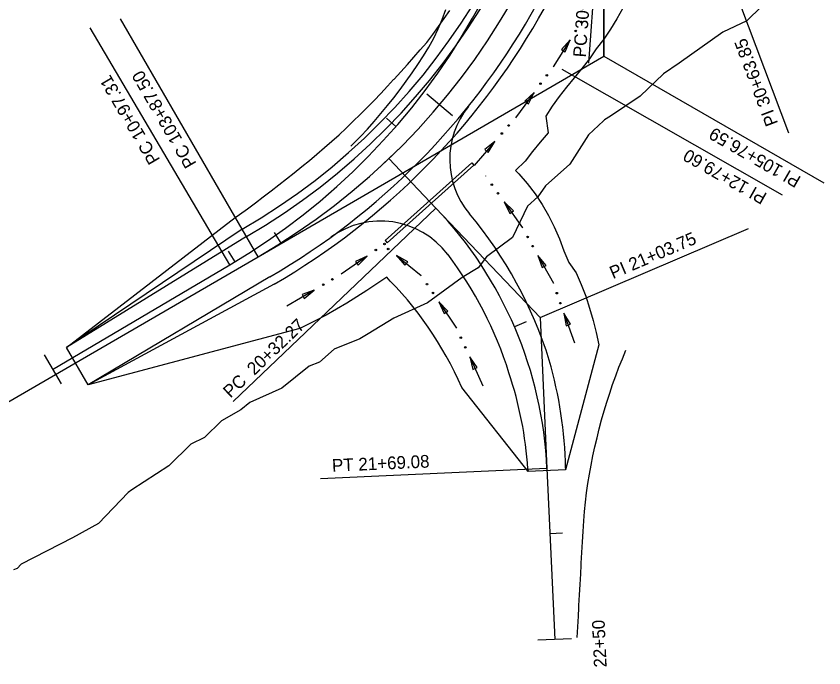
# Model space of a CAD drawing. Extents: x 1395202 to 1465904, y 1787951 to 1846942.
# Drawn here: x 1405502.4 to 1405884.5, y 1842049.9 to 1842358 of the extents above; entities that cross this region are included whole.
import ezdxf

# ---------------------------------------------------------------- set-up
doc = ezdxf.new("R2010")
doc.units = 0
for name, color, linetype in [('R_Drainage', 7, 'Continuous'), ('R_Horiz Alg Tangents', 7, 'Continuous'), ('R_Horz Alg', 7, 'Continuous'), ('R_Horz Alg Annot', 7, 'Continuous'), ('R_Horz Alg Stationing', 7, 'Continuous'), ('R_Perimeter', 7, 'Continuous'), ('R_Proposed Lane', 7, 'Continuous'), ('R_Proposed Shoulder', 7, 'Continuous'), ('R_SFHA', 7, 'Continuous'), ('R_Special Ditch', 7, 'Continuous'), ('R_Temp Perimeter', 7, 'Continuous'), ('R_Temp_Horz Alg', 7, 'Continuous'), ('R_Temp_Horz Alg Annot', 7, 'Continuous'), ('R_Temp_Horz Alg Stationing', 7, 'Continuous')]:
    doc.layers.add(name, color=color, linetype=linetype)

msp = doc.modelspace()

# ---------------------------------------------------------------- linework, layer by layer
at = {"layer": 'R_Drainage'}
for p, q in [((1405717.91, 1842288.66), (1405676.92, 1842251.99)), ((1405677.92, 1842250.87), (1405718.91, 1842287.54)), ((1405717.91, 1842288.66), (1405718.91, 1842287.54)), ((1405676.92, 1842251.99), (1405677.92, 1842250.87))]:
    msp.add_line(p, q, dxfattribs=at)
at = {"layer": 'R_Horiz Alg Tangents'}
for p, q in [((1405780.46, 1842339.07), (1405780.08, 1842528.16)), ((1405616.87, 1842244.24), (1405780.46, 1842339.07)), ((1405700.98, 1842267.28), (1405750.29, 1842215.53)), ((1405750.29, 1842215.53), (1405753.51, 1842144.12))]:
    msp.add_line(p, q, dxfattribs=at)
at = {"layer": 'R_Horz Alg'}
for p, q in [((1405678.71, 1842290.65), (1405700.98, 1842267.28)), ((1405281.62, 1842049.91), (1405616.87, 1842244.24)), ((1405281.62, 1842049.91), (1405616.87, 1842244.24)), ((1405753.51, 1842144.12), (1405757.15, 1842063.28))]:
    msp.add_line(p, q, dxfattribs=at)
for centre, radius, start, end in [((1405452.67, 1842527.5), 327.4, 300.1, 0.1167), ((1405452.67, 1842527.5), 327.4, 300.1, 0.1167), ((1405562.72, 1842135.53), 190.99, 2.5781, 43.6197)]:
    msp.add_arc(centre, radius, start, end, dxfattribs=at)
at = {"layer": 'R_Horz Alg Annot'}
for p in [(1405780.08, 1842528.16), (1405616.87, 1842244.24)]:
    msp.add_line(p, (1405780.46, 1842339.07), dxfattribs=at)
for points in [[(1405773.28, 1842335.74), (1405779.36, 1842418.47)], [(1405825.52, 1842415.08), (1405867.82, 1842302.78)], [(1405616.87, 1842244.24), (1405551.67, 1842356.71)], [(1405780.46, 1842339.07), (1405884.5, 1842279.27)], [(1405700.98, 1842267.28), (1405605.03, 1842175.85)], [(1405750.29, 1842215.53), (1405848.89, 1842257.58)], [(1405753.51, 1842144.12), (1405646.39, 1842139.29)]]:
    msp.add_lwpolyline(points, dxfattribs=at)
at = {"layer": 'R_Horz Alg Stationing'}
for points in [[(1405696.59, 1842321.28), (1405708.8, 1842310.95)], [(1405684.51, 1842296.16), (1405672.92, 1842285.13)], [(1405624.36, 1842255.79), (1405627.56, 1842250.72)], [(1405743.64, 1842213.45), (1405738.13, 1842211.08)], [(1405760.89, 1842113.5), (1405754.9, 1842113.23)], [(1405765.14, 1842063.64), (1405749.16, 1842062.92)], [(1405765.14, 1842063.64), (1405749.16, 1842062.92)]]:
    msp.add_lwpolyline(points, dxfattribs=at)
at = {"layer": 'R_Perimeter'}
for points in [[(1405795.43, 1842372.67), (1405792.23, 1842366.72), (1405789.39, 1842361.72), (1405786.53, 1842356.75), (1405783.6, 1842351.82), (1405780.37, 1842347.06), (1405776.85, 1842342.5), (1405773.55, 1842337.82), (1405770.06, 1842333.29), (1405766.44, 1842328.85), (1405762.82, 1842324.45), (1405759.31, 1842319.99), (1405756.04, 1842315.37), (1405752.92, 1842310.65), (1405754.04, 1842302.76), (1405750.24, 1842298.44), (1405746.69, 1842293.94), (1405743.16, 1842289.42), (1405738.65, 1842285.06)], [(1405677.68, 1842234.59), (1405673.04, 1842231.44), (1405668.33, 1842228.35), (1405663.57, 1842225.32), (1405658.77, 1842222.37), (1405653.94, 1842219.49), (1405649.06, 1842216.7), (1405644.09, 1842214.06), (1405639.06, 1842211.54), (1405636.54, 1842210.31), (1405536.36, 1842183.72), (1405526.19, 1842201.28), (1405606.06, 1842262.88), (1405607.97, 1842264.24), (1405611.77, 1842266.98), (1405615.54, 1842269.75), (1405619.27, 1842272.54), (1405622.98, 1842275.36), (1405626.66, 1842278.2), (1405630.32, 1842281.07), (1405633.96, 1842283.95), (1405637.57, 1842286.85), (1405641.15, 1842289.8), (1405644.69, 1842292.79), (1405648.19, 1842295.83), (1405651.67, 1842298.87), (1405655.14, 1842301.94), (1405658.51, 1842305.11), (1405661.83, 1842308.33), (1405665.15, 1842311.56), (1405668.43, 1842314.82), (1405671.67, 1842318.13), (1405674.86, 1842321.48), (1405678.04, 1842324.84), (1405680.97, 1842327.99), (1405681.2, 1842328.23), (1405684.33, 1842331.64), (1405687.45, 1842335.08), (1405690.52, 1842338.56), (1405693.58, 1842342.06), (1405696.61, 1842345.59), (1405699.47, 1842349.25), (1405702.17, 1842353.04), (1405704.84, 1842356.85), (1405707.48, 1842360.67)], [(1405738.65, 1842285.06), (1405740.19, 1842283.4), (1405744.19, 1842278.85), (1405747.88, 1842274.05), (1405751.21, 1842268.99), (1405754.23, 1842263.74), (1405756.97, 1842258.34), (1405759.39, 1842252.78), (1405761.53, 1842247.1), (1405763.91, 1842241.61), (1405767.27, 1842236.63), (1405769.76, 1842231.2), (1405771.85, 1842225.6), (1405773.66, 1842219.9), (1405775.34, 1842214.18), (1405776.81, 1842208.42), (1405778.04, 1842202.6), (1405762.34, 1842143.59), (1405744.58, 1842142.79), (1405713.2, 1842182.4), (1405711.51, 1842186.19), (1405709.75, 1842189.92), (1405707.85, 1842193.58), (1405705.88, 1842197.19), (1405703.83, 1842200.74), (1405701.69, 1842204.22), (1405699.49, 1842207.65), (1405697.23, 1842211.02), (1405694.92, 1842214.34), (1405692.54, 1842217.6), (1405690.06, 1842220.78), (1405687.47, 1842223.86), (1405684.82, 1842226.88), (1405682.13, 1842229.84), (1405679.37, 1842232.72), (1405677.68, 1842234.59)]]:
    msp.add_lwpolyline(points, dxfattribs=at)
at = {"layer": 'R_Proposed Lane'}
for p, q in [((1405611.35, 1842253.76), (1405526.19, 1842201.28)), ((1405622.38, 1842234.73), (1405536.36, 1842183.72)), ((1405744.49, 1842143.85), (1405744.58, 1842142.79)), ((1405762.33, 1842144.38), (1405762.34, 1842143.59))]:
    msp.add_line(p, q, dxfattribs=at)
for centre, radius, start, end in [((1405452.67, 1842527.5), 316.4, 300.1, 0.1338), ((1405452.67, 1842527.5), 338.4, 300.1, 0.1338), ((1405747.47, 1842290.25), 40, 141.1743, 219.9455), ((1405562.72, 1842135.53), 200.99, 17.3015, 39.9455), ((1405674.75, 1842221.11), 40, 37.3772, 125.9364), ((1405562.72, 1842135.53), 180.99, 17.3015, 37.3772), ((1405561.39, 1842139.97), 200.99, 1.2571, 15.9806), ((1405563.9, 1842131.86), 180.99, 3.7991, 18.5225)]:
    msp.add_arc(centre, radius, start, end, dxfattribs=at)
at = {"layer": 'R_Proposed Shoulder'}
for p, q in [((1405609.35, 1842257.22), (1405526.19, 1842201.28)), ((1405624.39, 1842231.26), (1405536.36, 1842183.72))]:
    msp.add_line(p, q, dxfattribs=at)
for radius in [312.4, 342.4]:
    msp.add_arc((1405452.67, 1842527.5), radius, 300.1, 0.1338, dxfattribs=at)
at = {"layer": 'R_SFHA'}
msp.add_lwpolyline([(1405862.03, 1842369.6), (1405848.1, 1842355.77), (1405836.65, 1842350.47), (1405816.09, 1842335.77), (1405808.69, 1842330.79), (1405797.53, 1842320.09), (1405783.6, 1842310.72), (1405780.73, 1842308.94), (1405780.27, 1842308.51), (1405773.16, 1842301.94), (1405764.38, 1842287.95), (1405752.8, 1842277.77), (1405749.2, 1842272.52), (1405744.34, 1842268.16), (1405737.18, 1842253.3), (1405724.87, 1842244.21), (1405720.98, 1842239.08), (1405713.38, 1842234.37), (1405696.91, 1842222.52), (1405681.06, 1842215.17), (1405668.93, 1842207.82), (1405664.91, 1842205.37), (1405652.88, 1842200.49), (1405645.92, 1842194.48), (1405640.95, 1842192.58), (1405628.11, 1842182.2), (1405612.98, 1842175.36), (1405608.67, 1842171.86), (1405599.47, 1842166.63), (1405591.52, 1842158.78), (1405585.01, 1842155.71), (1405574.62, 1842145.4), (1405557.05, 1842134.12), (1405555.36, 1842132.8), (1405541.29, 1842118.07), (1405529.1, 1842111.38), (1405504.74, 1842098.95), (1405502.81, 1842096.91), (1405501.12, 1842096.2)], dxfattribs=at)
at = {"layer": 'R_Special Ditch'}
for p, q in [((1405764.46, 1842346.74), (1405756.44, 1842334.06)), ((1405764.46, 1842346.74), (1405760.35, 1842342.23)), ((1405762.14, 1842341.1), (1405764.46, 1842346.74)), ((1405760.35, 1842342.23), (1405762.14, 1842341.1)), ((1405756.43, 1842334.05), (1405756.45, 1842334.08)), ((1405747.52, 1842321.98), (1405738.61, 1842309.91)), ((1405747.52, 1842321.98), (1405743.1, 1842317.78)), ((1405744.8, 1842316.52), (1405747.52, 1842321.98)), ((1405743.1, 1842317.78), (1405744.8, 1842316.52)), ((1405738.72, 1842310.04), (1405738.75, 1842310.07)), ((1405728.87, 1842298.73), (1405719.02, 1842287.41)), ((1405728.87, 1842298.73), (1405724.14, 1842294.9)), ((1405725.73, 1842293.51), (1405728.87, 1842298.73)), ((1405724.14, 1842294.9), (1405725.73, 1842293.51)), ((1405724.53, 1842282.42), (1405724.51, 1842282.45)), ((1405733.24, 1842270.21), (1405741.96, 1842258)), ((1405733.24, 1842270.21), (1405735.87, 1842264.71)), ((1405737.59, 1842265.94), (1405733.24, 1842270.21)), ((1405735.87, 1842264.71), (1405737.59, 1842265.94)), ((1405741.95, 1842258), (1405741.94, 1842258.03)), ((1405680.74, 1842253.14), (1405680.77, 1842253.16)), ((1405668.44, 1842244.55), (1405656.14, 1842235.96)), ((1405668.44, 1842244.55), (1405662.92, 1842241.98)), ((1405662.92, 1842241.98), (1405664.13, 1842240.25)), ((1405664.13, 1842240.25), (1405668.44, 1842244.55)), ((1405682.32, 1842244.84), (1405694.01, 1842235.44)), ((1405682.32, 1842244.84), (1405686.33, 1842240.25)), ((1405687.66, 1842241.9), (1405682.32, 1842244.84)), ((1405686.33, 1842240.25), (1405687.66, 1842241.9)), ((1405749.24, 1842244.88), (1405756.52, 1842231.77)), ((1405749.24, 1842244.88), (1405751.23, 1842239.13)), ((1405753.08, 1842240.15), (1405749.24, 1842244.88)), ((1405751.23, 1842239.13), (1405753.08, 1842240.15)), ((1405656.29, 1842236.05), (1405656.33, 1842236.07)), ((1405694, 1842235.43), (1405693.98, 1842235.47)), ((1405756.53, 1842231.75), (1405756.51, 1842231.79)), ((1405643.35, 1842228.47), (1405630.4, 1842220.89)), ((1405643.35, 1842228.47), (1405637.64, 1842226.35)), ((1405637.64, 1842226.35), (1405638.7, 1842224.53)), ((1405638.7, 1842224.53), (1405643.35, 1842228.47)), ((1405702.37, 1842222.99), (1405710.74, 1842210.54)), ((1405702.37, 1842222.99), (1405704.84, 1842217.42)), ((1405706.6, 1842218.6), (1405702.37, 1842222.99)), ((1405704.84, 1842217.42), (1405706.6, 1842218.6)), ((1405761.55, 1842217.62), (1405766.58, 1842203.49)), ((1405761.55, 1842217.62), (1405762.57, 1842211.61)), ((1405764.56, 1842212.32), (1405761.55, 1842217.62)), ((1405762.57, 1842211.61), (1405764.56, 1842212.32)), ((1405710.74, 1842210.52), (1405710.73, 1842210.55)), ((1405716.95, 1842196.86), (1405723.16, 1842183.21)), ((1405716.95, 1842196.86), (1405718.47, 1842190.96)), ((1405720.4, 1842191.84), (1405716.95, 1842196.86)), ((1405718.47, 1842190.96), (1405720.4, 1842191.84))]:
    msp.add_line(p, q, dxfattribs=at)
msp.add_lwpolyline([(1405767.82, 1842064.32), (1405768.09, 1842069.33), (1405768.37, 1842074.34), (1405768.59, 1842078.25), (1405768.59, 1842078.25), (1405768.65, 1842079.35), (1405768.92, 1842084.36), (1405769.2, 1842089.38), (1405769.48, 1842094.39), (1405769.71, 1842098.5), (1405769.76, 1842099.4), (1405770.03, 1842104.41), (1405770.31, 1842109.42), (1405770.59, 1842114.43), (1405770.87, 1842119.36), (1405771.22, 1842123.82), (1405771.68, 1842128.26), (1405772.22, 1842132.67), (1405772.87, 1842137.07), (1405773.59, 1842141.44), (1405774.39, 1842145.79), (1405775.25, 1842150.12), (1405776.18, 1842154.42), (1405777.18, 1842158.7), (1405778.25, 1842162.95), (1405779.38, 1842167.18), (1405780.58, 1842171.38), (1405781.85, 1842175.56), (1405783.18, 1842179.71), (1405784.58, 1842183.83), (1405786.04, 1842187.92), (1405787.57, 1842191.99), (1405789.16, 1842196.03), (1405790.82, 1842200.04)], dxfattribs=at)
for centre in [(1405769.78, 1842355.22), (1405767.1, 1842350.99), (1405753.44, 1842330.06), (1405750.46, 1842326.03), (1405735.42, 1842306.31), (1405732.13, 1842302.53), (1405727.4, 1842278.34), (1405730.31, 1842274.26), (1405744.34, 1842253.62), (1405676.63, 1842250.32), (1405746.78, 1842249.24), (1405672.52, 1842247.45), (1405678.39, 1842247.94), (1405651.97, 1842233.56), (1405647.65, 1842231.03), (1405696.75, 1842231.28), (1405699.55, 1842227.12), (1405758.16, 1842227.04), (1405759.84, 1842222.32), (1405712.77, 1842205.97), (1405714.85, 1842201.4)]:
    msp.add_circle(centre, 0.375, dxfattribs=at)
at = {"layer": 'R_Temp Perimeter'}
msp.add_lwpolyline([(1405660.76, 1842296.57), (1405661.82, 1842297.66), (1405665.25, 1842301.1), (1405668.58, 1842304.63), (1405671.8, 1842308.27), (1405674.94, 1842311.97), (1405678.04, 1842315.7), (1405681.13, 1842319.44), (1405684.08, 1842323.29), (1405686.93, 1842327.22), (1405689.75, 1842331.16), (1405692.48, 1842335.17), (1405695.07, 1842339.26), (1405697.58, 1842343.4), (1405699.91, 1842347.66), (1405702.06, 1842352.01), (1405703.97, 1842356.48), (1405705.64, 1842361.07)], dxfattribs=at)
at = {"layer": 'R_Temp_Horz Alg'}
msp.add_line((1405519.61, 1842190.99), (1405603.44, 1842240.41), dxfattribs=at)
msp.add_arc((1405441.79, 1842514.62), 318.31, 300.5194, 0.1167, dxfattribs=at)
at = {"layer": 'R_Temp_Horz Alg Annot'}
for points in [[(1405603.44, 1842240.41), (1405537.42, 1842352.4)], [(1405760.47, 1842332.98), (1405864.73, 1842273.56)]]:
    msp.add_lwpolyline(points, dxfattribs=at)
at = {"layer": 'R_Temp_Horz Alg Stationing'}
for points in [[(1405677.51, 1842309.74), (1405682.04, 1842305.8)], [(1405602.66, 1842246.93), (1405605.75, 1842241.78)], [(1405515.55, 1842197.88), (1405523.67, 1842184.1)]]:
    msp.add_lwpolyline(points, dxfattribs=at)

# ---------------------------------------------------------------- texts
at = {"layer": 'R_Horz Alg Annot'}
for s, rotation, p in [('PC 30+17.56', 85.8008, (1405771.83, 1842338.37)), ('PI 30+63.85', 110.6392, (1405862.9, 1842307.34)), ('PC 103+87.50', 120.1, (1405587.84, 1842288.34)), ('PI 105+76.59', 150.1083, (1405874.1, 1842281.79)), ('PI 21+03.75', 23.0989, (1405784.73, 1842233.62)), ('PC  20+32.27', 43.6197, (1405603.76, 1842177.15)), ('PT 21+69.08', 2.5781, (1405651.92, 1842142.55))]:
    msp.add_text(s, height=6, rotation=rotation, dxfattribs=at).set_placement(p)
at = {"layer": 'R_Horz Alg Stationing'}
msp.add_text('22+50', height=6, rotation=92.5781, dxfattribs=at).set_placement((1405781.76, 1842050.21))
at = {"layer": 'R_Temp_Horz Alg Annot'}
for s, rotation, p in [('PC 10+97.31', 120.5194, (1405570.64, 1842290.14)), ('PI 12+79.60', 150.3181, (1405858.03, 1842273.92))]:
    msp.add_text(s, height=6, rotation=rotation, dxfattribs=at).set_placement(p)

doc.saveas('drawing.dxf')
